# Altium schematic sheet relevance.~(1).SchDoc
size A2
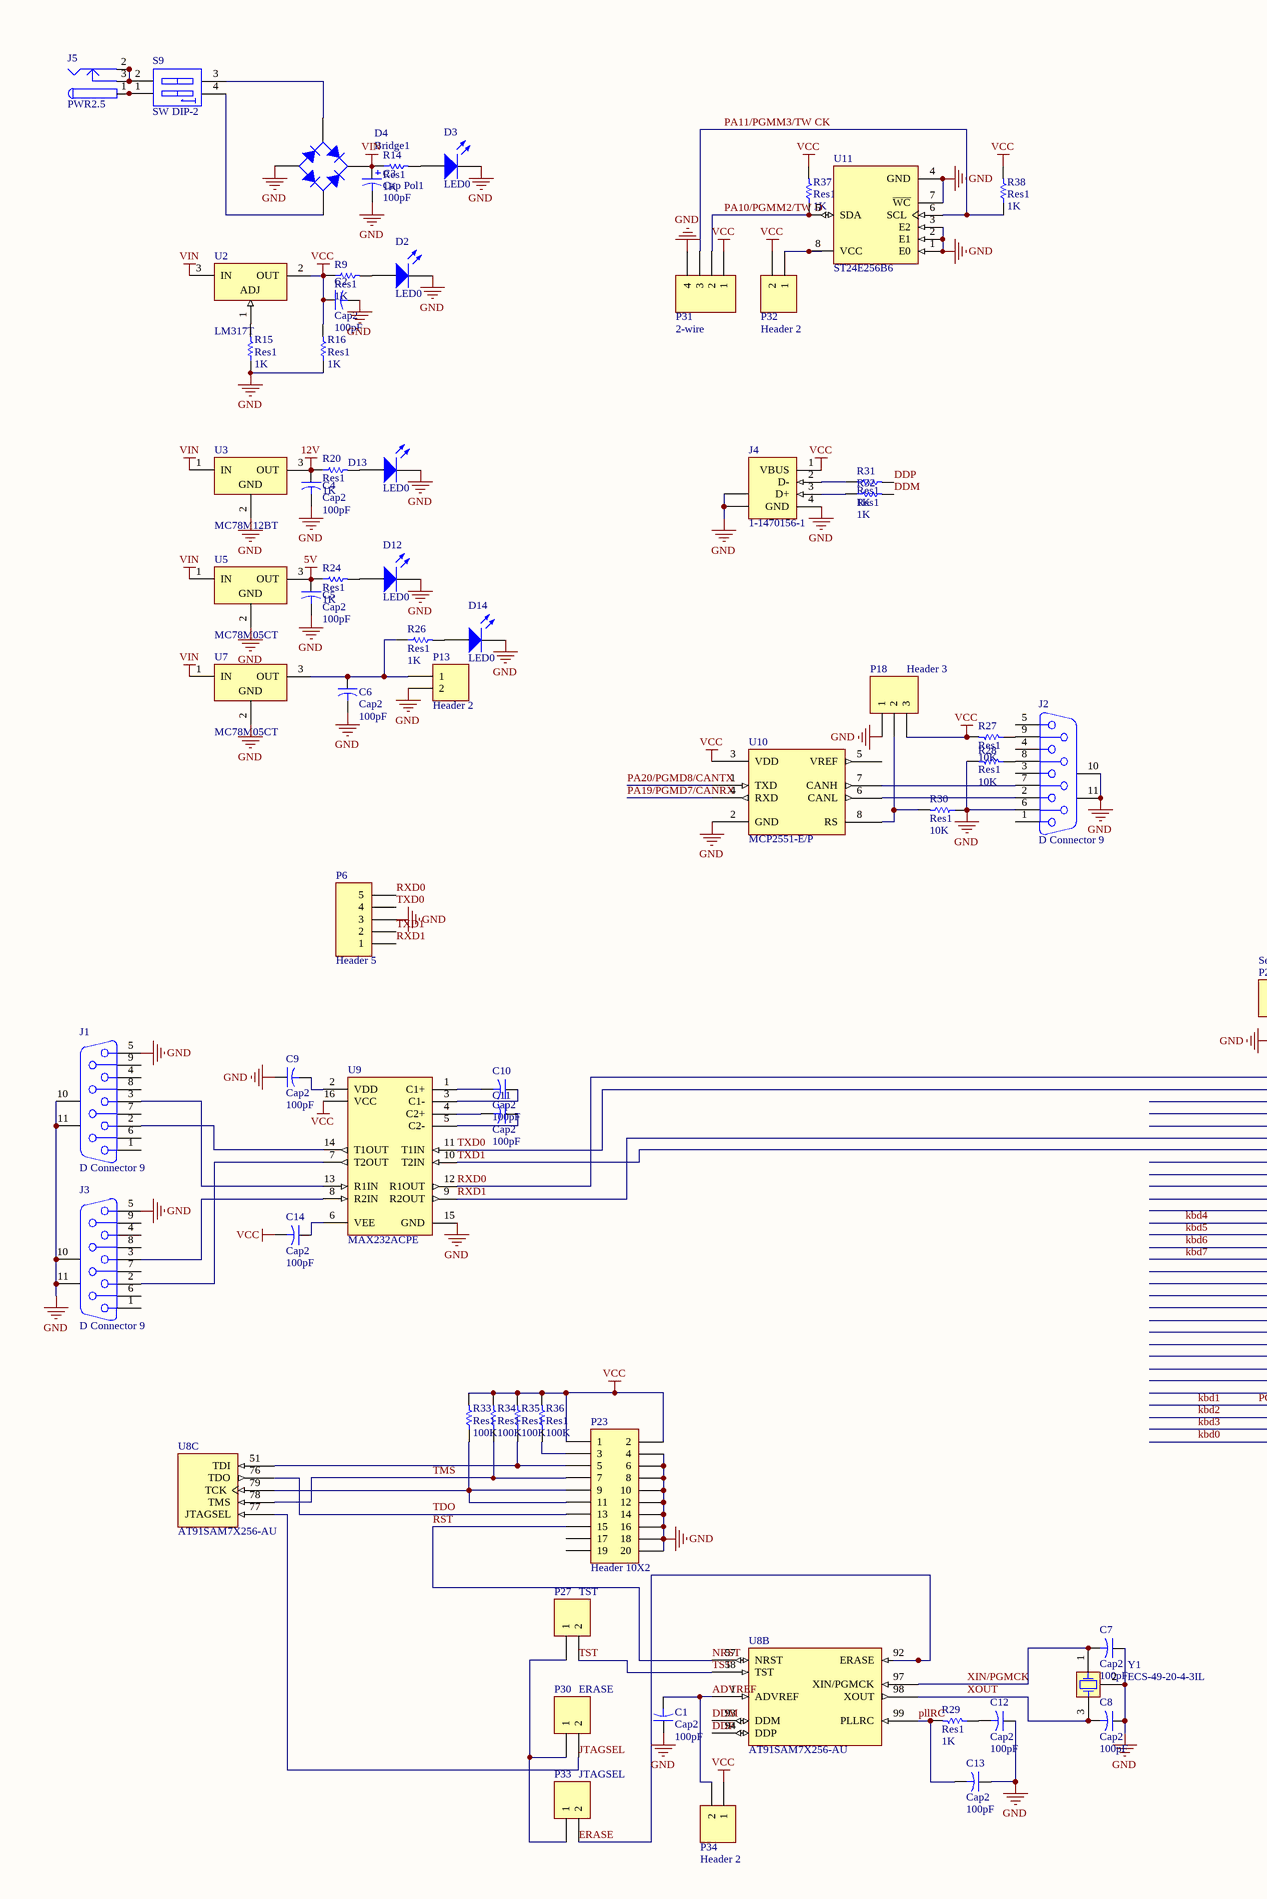
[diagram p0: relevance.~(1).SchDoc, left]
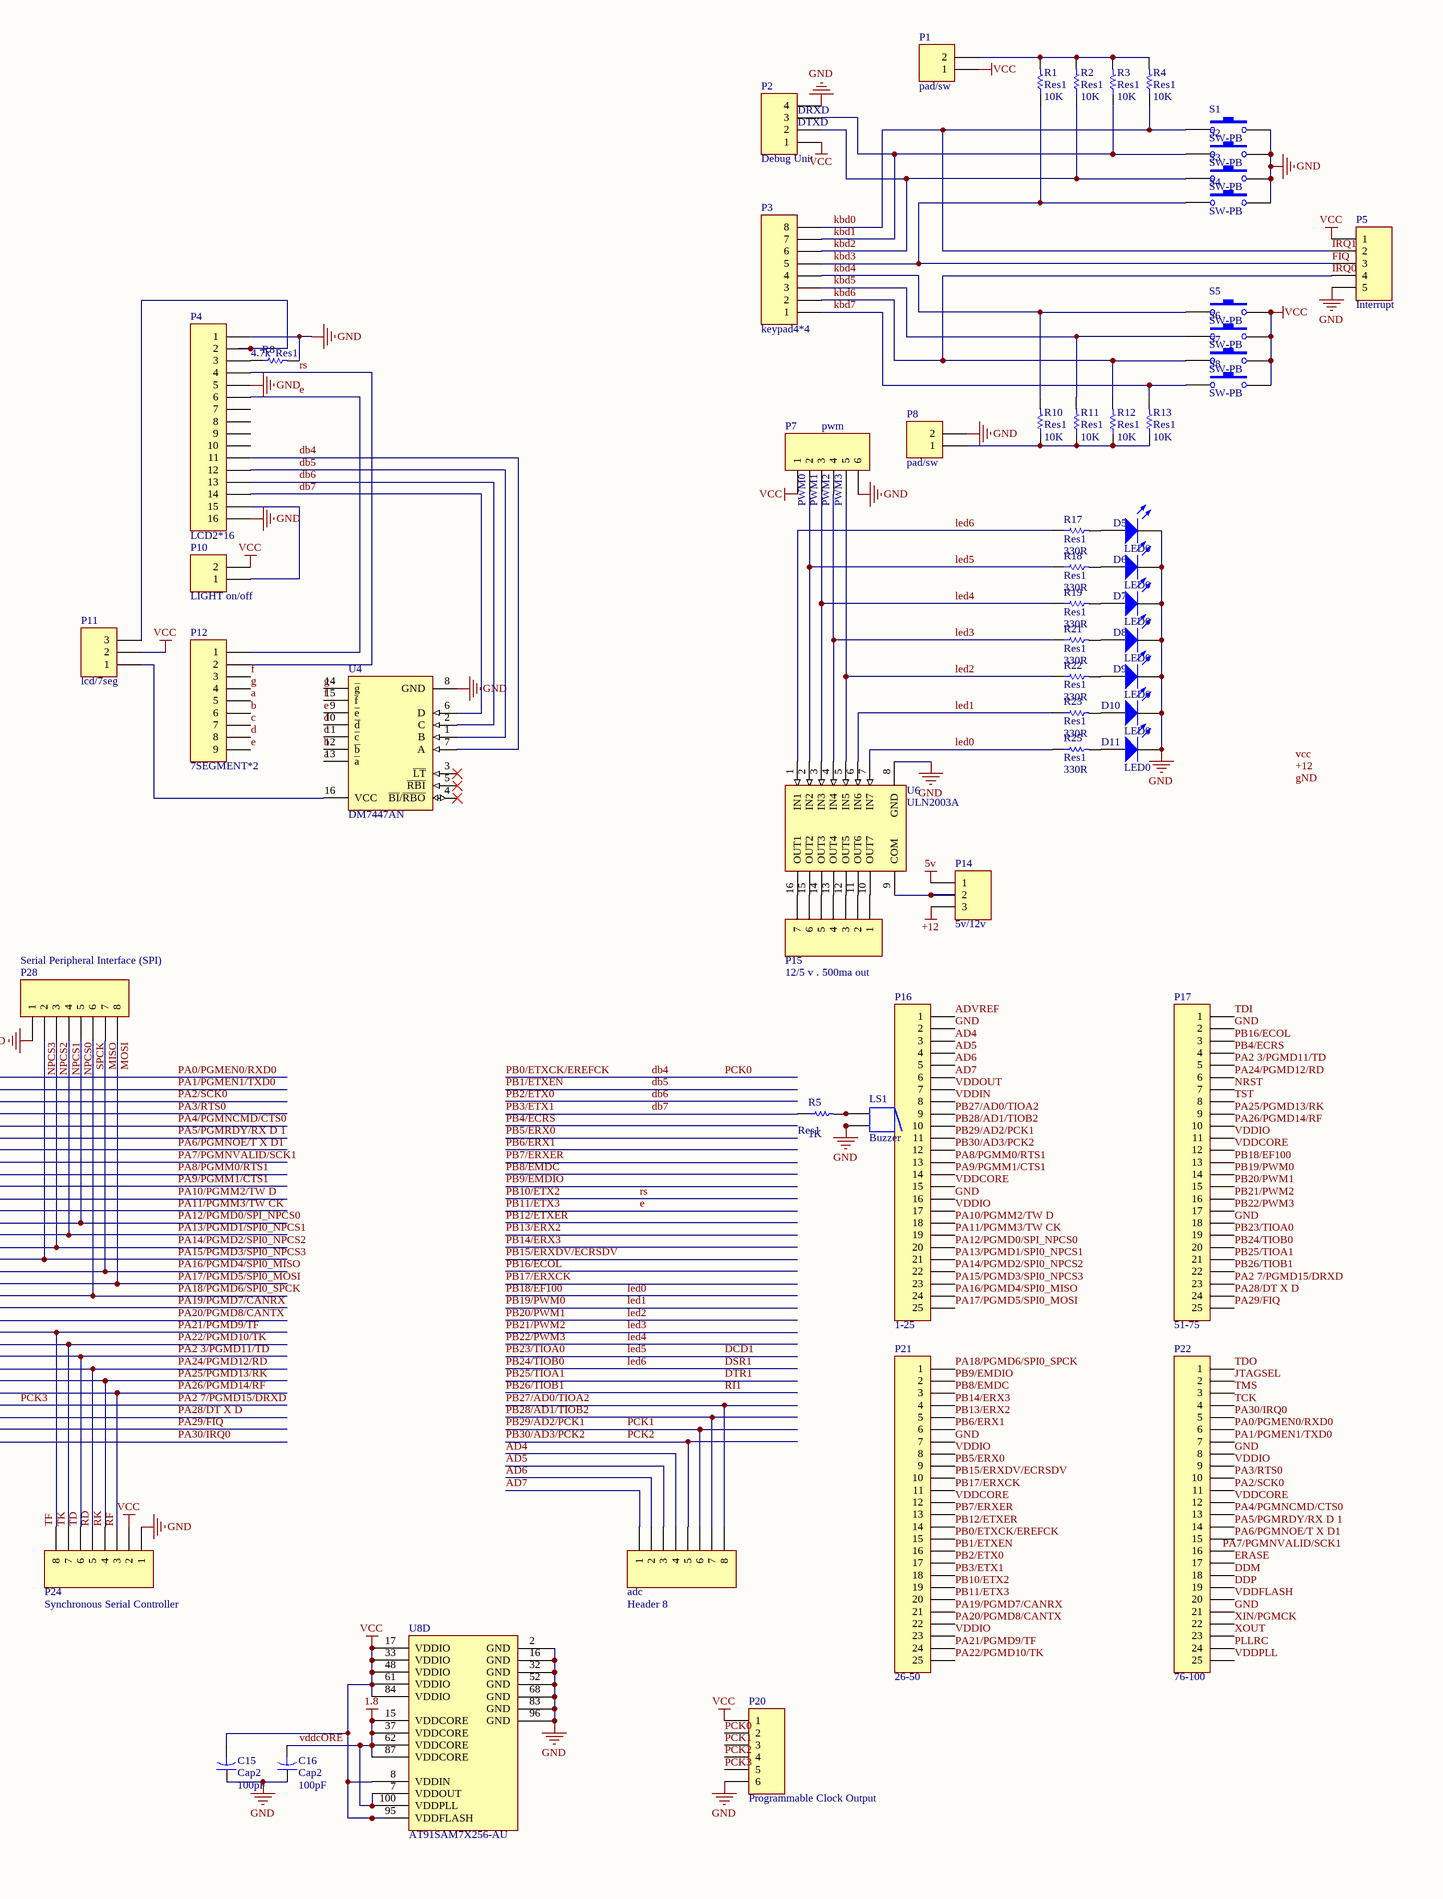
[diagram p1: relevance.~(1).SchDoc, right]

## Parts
adc  Header 8  [HDR1X8]
C1  Cap2  value 100pF  [CAPR5-4X5]
C2  Cap2  value 100pF  [CAPR5-4X5]
C3  Cap Pol1  value 100pF  [RB7.6-15]
C4  Cap2  value 100pF  [CAPR5-4X5]
C5  Cap2  value 100pF  [CAPR5-4X5]
C6  Cap2  value 100pF  [CAPR5-4X5]
C7  Cap2  value 100pF  [CAPR5-4X5]
C8  Cap2  value 100pF  [CAPR5-4X5]
C9  Cap2  value 100pF  [CAPR5-4X5]
C10  Cap2  value 100pF  [CAPR5-4X5]
C11  Cap2  value 100pF  [CAPR5-4X5]
C12  Cap2  value 100pF  [CAPR5-4X5]
C13  Cap2  value 100pF  [CAPR5-4X5]
C14  Cap2  value 100pF  [CAPR5-4X5]
C15  Cap2  value 100pF  [CAPR5-4X5]
C16  Cap2  value 100pF  [CAPR5-4X5]
D2  LED0  [LED-0]
D3  LED0  [LED-0]
D4  Bridge1  [D-38]
D5  LED0  [LED-0]
D6  LED0  [LED-0]
D7  LED0  [LED-0]
D8  LED0  [LED-0]
D9  LED0  [LED-0]
D10  LED0  [LED-0]
D11  LED0  [LED-0]
D12  LED0  [LED-0]
D13  LED0  [LED-0]
D14  LED0  [LED-0]
J1  D Connector 9  [DSUB1.385-2H9]
J2  D Connector 9  [DSUB1.385-2H9]
J3  D Connector 9  [DSUB1.385-2H9]
J4  1-1470156-1  [1-1470156]
J5  PWR2.5  [KLD-0202]
LS1  Buzzer  [ABSM-1574]
P1  pad/sw  [HDR1X2]
P2  Debug Unit  [HDR1X4]
P3  keypad4*4  [HDR1X8]
P4  LCD2*16  [HDR1X16]
P5  Interrupt  [HDR1X5]
P6  Header 5  [HDR1X5]
P7  pwm  [HDR1X6]
P8  pad/sw  [HDR1X2]
P10  LIGHT on/off  [HDR1X2]
P11  lcd/7seg  [HDR1X3]
P12  7SEGMENT*2  [HDR1X9]
P13  Header 2  [HDR1X2]
P14  5v/12v  [HDR1X3]
P15  12/5 v . 500ma out  [HDR1X7]
P16  1-25  [HDR1X25]
P17  51-75  [HDR1X25]
P18  Header 3  [HDR1X3]
P20  Programmable Clock Output  [HDR1X6]
P21  26-50  [HDR1X25]
P22  76-100  [HDR1X25]
P23  Header 10X2  [HDR2X10]
P24  Synchronous Serial Controller  [HDR1X8]
P27  TST  [HDR1X2]
P28  Serial Peripheral Interface (SPI)  [HDR1X8]
P30  ERASE  [HDR1X2]
P31  2-wire  [HDR1X4]
P32  Header 2  [HDR1X2]
P33  JTAGSEL  [HDR1X2]
P34  Header 2  [HDR1X2]
R1  Res1  value 10K  [AXIAL-0.3]
R2  Res1  value 10K  [AXIAL-0.3]
R3  Res1  value 10K  [AXIAL-0.3]
R4  Res1  value 10K  [AXIAL-0.3]
R5  Res1  value 1K  [AXIAL-0.3]
R8  Res1  value 4.7k  [AXIAL-0.3]
R9  Res1  value 1K  [AXIAL-0.3]
R10  Res1  value 10K  [AXIAL-0.3]
R11  Res1  value 10K  [AXIAL-0.3]
R12  Res1  value 10K  [AXIAL-0.3]
R13  Res1  value 10K  [AXIAL-0.3]
R14  Res1  value 1K  [AXIAL-0.3]
R15  Res1  value 1K  [AXIAL-0.3]
R16  Res1  value 1K  [AXIAL-0.3]
R17  Res1  value 330R  [AXIAL-0.3]
R18  Res1  value 330R  [AXIAL-0.3]
R19  Res1  value 330R  [AXIAL-0.3]
R20  Res1  value 1K  [AXIAL-0.3]
R21  Res1  value 330R  [AXIAL-0.3]
R22  Res1  value 330R  [AXIAL-0.3]
R23  Res1  value 330R  [AXIAL-0.3]
R24  Res1  value 1K  [AXIAL-0.3]
R25  Res1  value 330R  [AXIAL-0.3]
R26  Res1  value 1K  [AXIAL-0.3]
R27  Res1  value 10K  [AXIAL-0.3]
R28  Res1  value 10K  [AXIAL-0.3]
R29  Res1  value 1K  [AXIAL-0.3]
R30  Res1  value 10K  [AXIAL-0.3]
R31  Res1  value 1K  [AXIAL-0.3]
R32  Res1  value 1K  [AXIAL-0.3]
R33  Res1  value 100K  [AXIAL-0.3]
R34  Res1  value 100K  [AXIAL-0.3]
R35  Res1  value 100K  [AXIAL-0.3]
R36  Res1  value 100K  [AXIAL-0.3]
R37  Res1  value 1K  [AXIAL-0.3]
R38  Res1  value 1K  [AXIAL-0.3]
S1  SW-PB  [SPST-2]
S2  SW-PB  [SPST-2]
S3  SW-PB  [SPST-2]
S4  SW-PB  [SPST-2]
S5  SW-PB  [SPST-2]
S6  SW-PB  [SPST-2]
S7  SW-PB  [SPST-2]
S8  SW-PB  [SPST-2]
S9  SW DIP-2  [DIP-4]
U2  LM317T  [221A-04]
U3  MC78M12BT  [221A-04]
U4  DM7447AN  [N16E]
U5  MC78M05CT  [221A-04]
U6  ULN2003A  [A16]
U7  MC78M05CT  [221A-04]
U8  AT91SAM7X256-AU  [LQFP100_N]  (parts B,C,D of 4)
U9  MAX232ACPE  [PE16A]
U10  MCP2551-E/P  [PDIP300-8]
U11  ST24E256B6  [PSDIP8A]
Y1  ECS-49-20-4-3IL  [HC-49US]

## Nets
5V: C5.1 P14.1 R24.1 U5.3(OUT)
12V: C4.1 R20.1 U3.3(OUT)
+12: P14.3
GND: C1.1 C2.2 C3.2 C4.2 C5.2 C6.2 C7.1 C8.1 C9.1 C12.1 C13.1 C15.1 C16.1 D2.2(K) D3.2(K) D4.1(A) D5.2(K) D6.2(K) D7.2(K) D8.2(K) D9.2(K) D10.2(K) D11.2(K) D12.2(K) D13.2(K) D14.2(K) J1.5 J1.10(MH1) J1.11(MH2) J2.6 J2.10(MH1) J2.11(MH2) J3.5 J3.10(MH1) J3.11(MH2) J4.4(GND) J4.5(SHLD) J4.6(SHLD) LS1.2 LS1.2A P2.4 P4.1 P4.5 P4.16 P5.5 P6.3 P7.6 P8.2 P13.2 P16.2 P16.16 P17.2 P17.18 P18.1 P20.6 P21.7 P22.8 P22.21 P23.4 P23.6 P23.8 P23.10 P23.12 P23.14 P23.16 P23.18 P23.20 P24.1 P28.1 P31.4 R8.2 R15.1 R16.1 R28.2 R30.1 S1.2 S2.2 S3.2 S4.2 U3.2(GND) U4.8(GND) U5.2(GND) U6.8(GND) U7.2(GND) U8.2(GND) U8.16(GND) U8.32(GND) U8.52(GND) U8.68(GND) U8.83(GND) U8.96(GND) U9.15(GND) U10.2(GND) U11.1(E0) U11.2(E1) U11.3(E2) U11.4(GND) U11.7(~{WC}) Y1.2(COM)
VCC: C2.1 C14.2 C15.2 J4.1(VBUS) P1.1 P2.1 P5.1 P7.1 P10.2 P11.2 P18.3 P20.1 P23.1 P23.2 P24.2 P31.1 P32.2 P34.1 R9.1 R16.2 R27.2 R33.2 R34.2 R35.2 R36.2 R37.2 R38.2 S5.2 S6.2 S7.2 S8.2 U2.2(OUT) U8.8(VDDIN) U8.17(VDDIO) U8.33(VDDIO) U8.48(VDDIO) U8.61(VDDIO) U8.84(VDDIO) U8.95(VDDFLASH) U9.16(VCC) U10.3(VDD)
VDDCORE: C16.2 P16.15 P17.12 P21.12 P22.12 U8.7(VDDOUT) U8.15(VDDCORE) U8.37(VDDCORE) U8.62(VDDCORE) U8.87(VDDCORE) U8.100(VDDPLL)  [also labelled 1.8]
VIN: C3.1 D4.3(K) R14.1 U2.3(IN) U3.1(IN) U5.1(IN) U7.1(IN)
a: P12.5 U4.13(~{a})
AD4: adc.4 P16.3
AD5: adc.3 P16.4
AD6: adc.2 P16.5
AD7: adc.1 P16.6
ADVREF: C1.2 P16.1 P34.2 U8.1(ADVREF)
b: P12.6 U4.12(~{b})
c: P12.7 U4.11(~{c})
d: P12.8 U4.10(~{d})
db4: P4.11 P20.2 P21.15 U4.7(A)  [also labelled PB0/ETXCK/EREFCK, PCK0]
db5: P4.12 P21.16 U4.1(B)  [also labelled PB1/ETXEN]
db6: P4.13 P21.17 U4.2(C)  [also labelled PB2/ETX0]
db7: P4.14 P21.18 R5.1 U4.6(D)  [also labelled PB3/ETX1]
DCD1: P7.2 P17.19 R18.1 U6.2(IN2)  [also labelled led5, PB23/TIOA0]
DDM: P22.18 R32.2 U8.93(DDM)
DDP: P22.19 R31.2 U8.94(DDP)
DSR1: P17.20 R17.1 U6.1(IN1)  [also labelled led6, PB24/TIOB0]
DTR1: P17.21  [also labelled PB25/TIOA1]
e: P4.6 P12.1 P12.9 P21.20 U4.9(~{e})  [also labelled PB11/ETX3]
ERASE: P22.17 P33.2 U8.92(ERASE)
f: P12.3 U4.15(~{f})
FIQ: P3.5 P5.3 P17.25 R1.1 S4.1  [also labelled kbd3, PA29/FIQ]
g: P12.4 U4.14(~{g})
IRQ0: P3.2 P5.4 P16.22 P28.3 R12.2 S7.1  [also labelled kbd6, NPCS2, PA14/PGMD2/SPI0_NPCS2]
IRQ1: P3.8 P5.2 P22.5 R4.1 S1.1  [also labelled kbd0, PA30/IRQ0]
JTAGSEL: P22.2 P30.2 U8.77(JTAGSEL)
kbd1: P2.3 P3.7 P17.23 P20.5 R3.1 S2.1  [also labelled PA2 7/PGMD15/DRXD, PCK3]
kbd2: P2.2 P3.6 P17.24 R2.1 S3.1  [also labelled PA28/DT X D]
kbd4: P3.4 P16.20 P28.5 R10.2 S5.1  [also labelled NPCS0, PA12/PGMD0/SPI_NPCS0]
kbd5: P3.3 P16.21 P28.4 R11.2 S6.1  [also labelled NPCS1, PA13/PGMD1/SPI0_NPCS1]
kbd7: P3.1 P16.23 P28.2 R13.2 S8.1  [also labelled NPCS3, PA15/PGMD3/SPI0_NPCS3]
led0: P17.13 R25.1 U6.7(IN7)  [also labelled PB18/EF100]
led1: P17.14 R23.1 U6.6(IN6)  [also labelled PB19/PWM0]
led2: P7.5 P17.15 R22.1 U6.5(IN5)  [also labelled PB20/PWM1]
led3: P7.4 P17.16 R21.1 U6.4(IN4)  [also labelled PB21/PWM2]
led4: P7.3 P17.17 R19.1 U6.3(IN3)  [also labelled PB22/PWM3]
MISO: P16.24 P28.7  [also labelled PA16/PGMD4/SPI0_MISO]
MOSI: P16.25 P28.8  [also labelled PA17/PGMD5/SPI0_MOSI]
NRST: P17.7 P23.15 U8.57(NRST)  [also labelled RST]
PA0/PGMEN0/RXD0: P6.5 P22.6 U9.12(R1OUT)  [also labelled RXD0]
PA1/PGMEN1/TXD0: P6.4 P22.7 U9.11(T1IN)  [also labelled TXD0]
PA2 3/PGMD11/TD: P17.5 P24.6  [also labelled TD]
PA2/SCK0: P22.11
PA3/RTS0: P22.10
PA4/PGMNCMD/CTS0: P22.13
PA5/PGMRDY/RX D 1: P6.1 P22.14 U9.9(R2OUT)  [also labelled RXD1]
PA6/PGMNOE/T X D1: P6.2 P22.15 U9.10(T2IN)  [also labelled TXD1]
PA8/PGMM0/RTS1: P16.13
PA9/PGMM1/CTS1: P16.14
PA10/PGMM2/TW D: P16.18 P31.2 R37.1 U11.5(SDA)
PA11/PGMM3/TW CK: P16.19 P31.3 R38.1 U11.6(SCL)
PA18/PGMD6/SPI0_SPCK: P21.1 P28.6  [also labelled SPCK]
PA19/PGMD7/CANRX: P21.21 U10.4(RXD)
PA20/PGMD8/CANTX: P21.22 U10.1(TXD)
PA21/PGMD9/TF: P21.24 P24.8  [also labelled TF]
PA22/PGMD10/TK: P21.25 P24.7  [also labelled TK]
PA24/PGMD12/RD: P17.6 P24.5  [also labelled RD]
PA25/PGMD13/RK: P17.9 P24.4  [also labelled RK]
PA26/PGMD14/RF: P17.10 P24.3  [also labelled RF]
PB4/ECRS: P17.4
PB5/ERX0: P21.9
PB6/ERX1: P21.6
PB7/ERXER: P21.13
PB8/EMDC: P21.3
PB9/EMDIO: P21.2
PB10/ETX2: P4.4 P12.2 P21.19  [also labelled rs]
PB12/ETXER: P21.14
PB13/ERX2: P21.5
PB14/ERX3: P21.4
PB15/ERXDV/ECRSDV: P21.10
PB16/ECOL: P17.3
PB17/ERXCK: P21.11
PB26/TIOB1: P17.22  [also labelled RI1]
PB27/AD0/TIOA2: adc.8 P16.9
PB28/AD1/TIOB2: adc.7 P16.10
PB29/AD2/PCK1: adc.6 P16.11 P20.3  [also labelled PCK1]
PB30/AD3/PCK2: adc.5 P16.12 P20.4  [also labelled PCK2]
PLLRC: C13.2 P22.24 R29.2 U8.99(PLLRC)
TCK: P22.4
TDI: P17.1
TDO: P22.1 P23.13 U8.76(TDO)
TMS: P22.3 P23.7 R34.1 U8.78(TMS)
TST: P17.8 P27.2 U8.58(TST)
VDDFLASH: P22.20
VDDIN: P16.8
VDDIO: P16.17 P17.11 P21.8 P21.23 P22.9
VDDOUT: P16.7
VDDPLL: P22.25
XIN/PGMCK: C7.2 P22.22 U8.97(XIN/PGMCK) Y1.1(OSC1)
XOUT: C8.2 P22.23 U8.98(XOUT) Y1.3(OSC2)
NetC6_1: C6.1 P13.1 R26.1 U7.3(OUT)
NetC9_2: C9.2 U9.2(VDD)
NetC10_1: C10.1 U9.3(C1-)
NetC10_2: C10.2 U9.1(C1+)
NetC11_1: C11.1 U9.5(C2-)
NetC11_2: C11.2 U9.4(C2+)
NetC12_2: C12.2 R29.1
NetC14_1: C14.1 U9.6(VEE)
NetD2_1: D2.1(A) R9.2
NetD3_1: D3.1(A) R14.2
NetD4_2: D4.2(C) S9.3(B2)
NetD4_4: D4.4(C) S9.4(B1)
NetD5_1: D5.1(A) R17.2
NetD6_1: D6.1(A) R18.2
NetD7_1: D7.1(A) R19.2
NetD8_1: D8.1(A) R21.2
NetD9_1: D9.1(A) R22.2
NetD10_1: D10.1(A) R23.2
NetD11_1: D11.1(A) R25.2
NetD12_1: D12.1(A) R24.2
NetD13_1: D13.1(A) R20.2
NetD14_1: D14.1(A) R26.2
NetJ1_2: J1.2 U9.14(T1OUT)
NetJ1_3: J1.3 U9.13(R1IN)
NetJ2_2: J2.2 U10.6(CANL)
NetJ2_7: J2.7 U10.7(CANH)
NetJ2_8: J2.8 R28.1
NetJ2_9: J2.9 R27.1
NetJ3_2: J3.2 U9.7(T2OUT)
NetJ3_3: J3.3 U9.8(R2IN)
NetJ4_2: J4.2(D-) R31.1
NetJ4_3: J4.3(D+) R32.1
NetJ5_1: J5.1 J5.1A J5.1B S9.1(A1)
NetJ5_2: J5.2 J5.2A J5.2B J5.3 J5.3A J5.3B S9.2(A2)
NetLS1_1: LS1.1 LS1.1A R5.2
NetP1_2: P1.2 R1.2 R2.2 R3.2 R4.2
NetP4_2: P4.2 P11.3
NetP4_3: P4.3 R8.1
NetP4_15: P4.15 P10.1
NetP8_1: P8.1 R10.1 R11.1 R12.1 R13.1
NetP11_1: P11.1 U4.16(VCC)
NetP14_2: P14.2 U6.9(COM)
NetP15_1: P15.1 U6.10(OUT7)
NetP15_2: P15.2 U6.11(OUT6)
NetP15_3: P15.3 U6.12(OUT5)
NetP15_4: P15.4 U6.13(OUT4)
NetP15_5: P15.5 U6.14(OUT3)
NetP15_6: P15.6 U6.15(OUT2)
NetP15_7: P15.7 U6.16(OUT1)
NetP18_2: P18.2 R30.2 U10.8(RS)
NetP23_3: P23.3 R36.1
NetP23_5: P23.5 R35.1 U8.51(TDI)
NetP23_9: P23.9 P23.11 R33.1 U8.79(TCK)
NetP27_1: P27.1 P30.1 P33.1
NetP32_1: P32.1 U11.8(VCC)
NetR15_2: R15.2 U2.1(ADJ)

Not connected (* = marked no-connect by the designer): J1 1 4 6 7 8 9; J2 1 3 4 5; J3 1 4 6 7 8 9; P4 7 8 9 10; P22 16; P23 17 19; U4 3(~{LT})* 4(~{BI}/~{RBO})* 5(~{RBI})*; U10 5(VREF)

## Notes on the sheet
- (near P2) DRXD
- (near P2) DTXD
- (near P7) PWM0
- (near P7) PWM1
- (near P7) PWM2
- (near P7) PWM3
- Labels drawn without touching a wire or pin: +12, gND, PA7/PGMNVALID/SCK1, vcc

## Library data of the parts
adc P3 P24 P28 = Header 8: Header, 8-Pin
C1 C2 C4-C16 = Cap2: Capacitor
C3 = Cap Pol1: Polarized Capacitor (Radial)
D2 D3 D5-D14 = LED0: Typical INFRARED GaAs LED
D4 = Bridge1: Full Wave Diode Bridge
J1-J3 = D Connector 9: Receptacle Assembly, 9 Position, Right Angle; PackageDocument: O; Positions: 9
J4 = 1-1470156-1: USB 1.1, Right Angle, Thru-Hole, B Type, Receptacle, 4 Position, White; ContactMaterial: Phosphor Bronze; ContactPlating: Gold over Nickel; TerminationLength: 3.00mm [0.118in.]; PCB_Layout: Complies with manufacturer's recommendation.; DrillSize: Corresponds to nominal value.; PanelGround: Without
J5 = PWR2.5: Low Voltage Power Supply Connector
LS1 = Buzzer: Magnetic Transducer Buzzer
P1 P8 P10 P13 P27 P30 P32-P34 = Header 2: Header, 2-Pin
P2 P31 = Header 4: Header, 4-Pin
P4 = Header 16: Header, 16-Pin
P5 P6 = Header 5: Header, 5-Pin
P7 P20 = Header 6: Header, 6-Pin
P11 P14 P18 = Header 3: Header, 3-Pin
P12 = Header 9: Header, 9-Pin
P15 = Header 7: Header, 7-Pin
P16 P17 P21 P22 = Header 25: Header, 25-Pin
P23 = Header 10X2: Header, 10-Pin, Dual row
R1-R5 R8-R38 = Res1: Resistor
S1-S8 = SW-PB: Switch
S9 = SW DIP-2: DIP Switch, 2 Position, SPST
U2 = LM317T: 3-Terminal Adjustable Positive Voltage Regulator; Note: Heatsink surface connected to pin 2.
U3 = MC78M12BT: 3-Terminal Medium-Current Positive Fixed Voltage Regulator; Note: Pin 2 is electrically connected to TAB
U4 = DM7447AN: BCD to 7-Segment Decoder/Driver
U5 U7 = MC78M05CT: 3-Terminal Medium-Current Positive Fixed Voltage Regulator; Note: Pin 2 is electrically connected to TAB
U6 = ULN2003A: High-Voltage, High-Current Darlington Array
U8 = AT91SAM7X256-AU: Smart ARM Microcontroller, ARM7TDMI 32-Bit RISC CPU, 256KB Flash and 64KB SRAM, 100-Pin LQFP, Industrial, Pb-Free
U9 = MAX232ACPE: +5V Powered, Multi-Channel RS-232 Driver/Receiver
U10 = MCP2551-E/P: High Speed CAN Transceiver, 8-Pin Plastic DIP, Extended Grade
U11 = ST24E256B6: Serial Access Extended Addressing Compatible with I²C Bus 256K (32K x 8) EEPROM
Y1 = ECS-49-20-4-3IL: Crystal Oscillator, 3rd In-Line Lead Version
